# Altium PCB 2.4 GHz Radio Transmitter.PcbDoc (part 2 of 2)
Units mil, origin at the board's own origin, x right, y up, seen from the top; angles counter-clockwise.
Board outline 5905.26 x 4050.27 mil, 4 copper layers (Top Layer, GND, Power, Bottom Layer), stack 63.355 mil thick; 215 components, 108 nets, 659 pads, 107 vias.
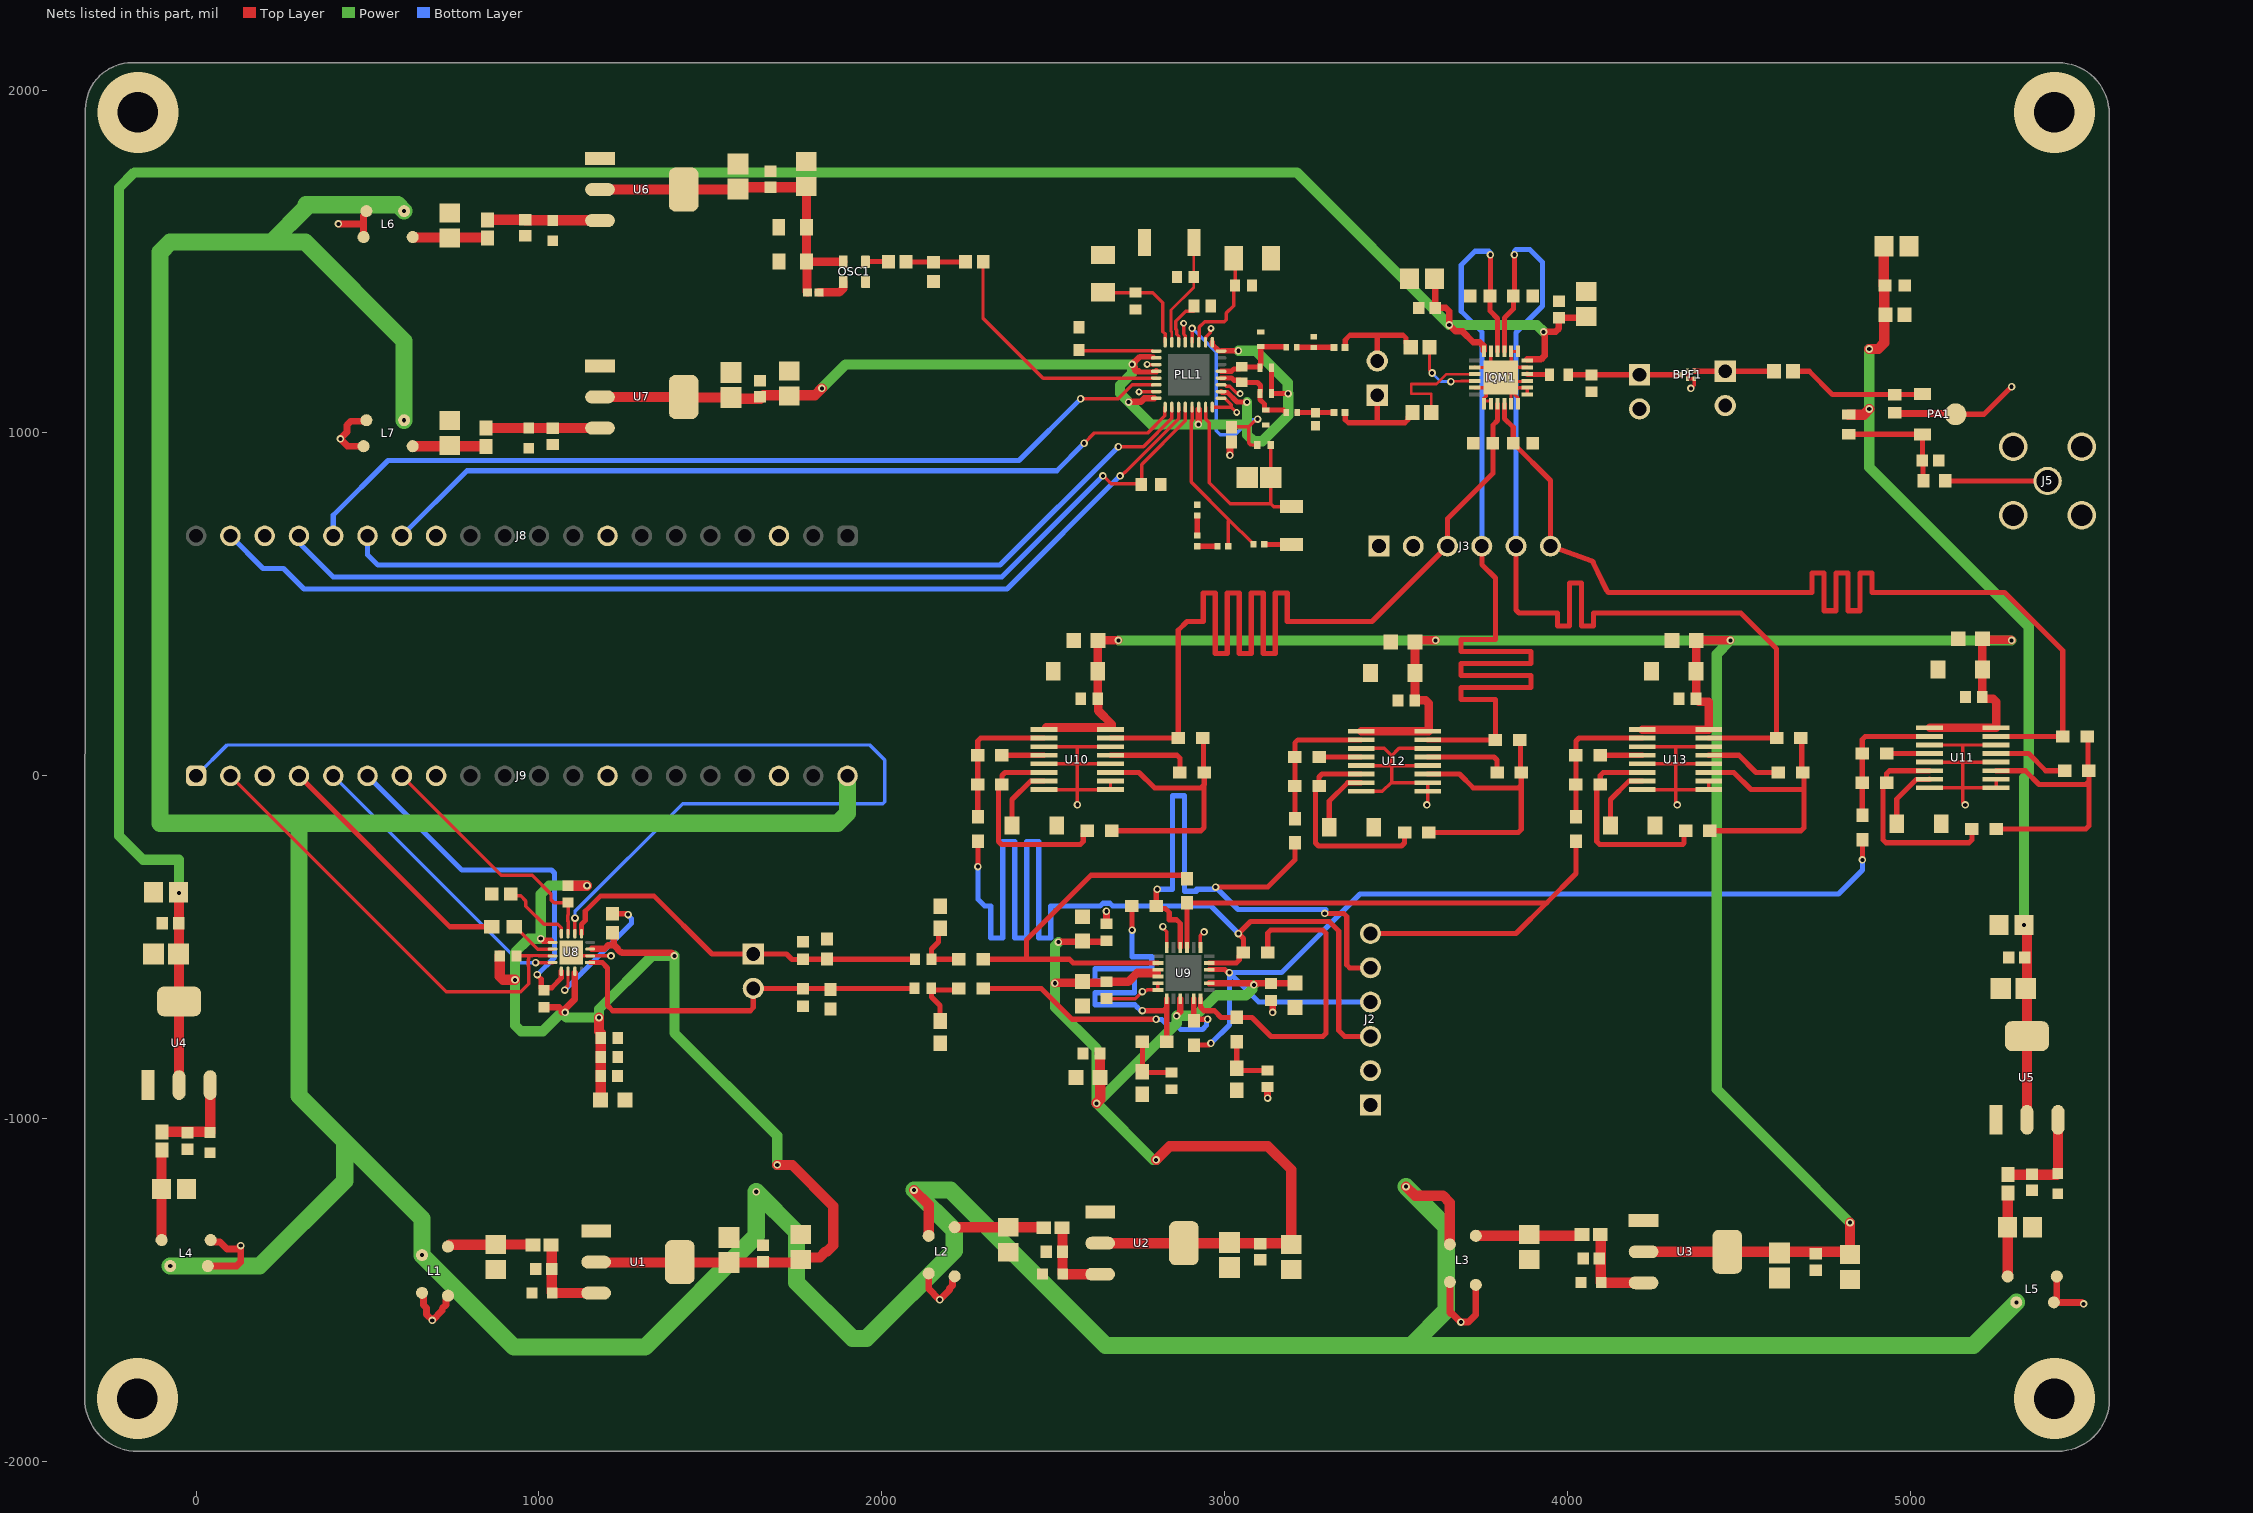
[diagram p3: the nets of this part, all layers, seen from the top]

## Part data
BPF1: library part CMP-034-000001-3, "Signal Conditioning LTCC BAND PASS FLTR 2400-2500MHz"
C1 C6 C7 C12 C13 C14 C23 C24 C25 C30 C31 C36 C37 C42 C92 C95: library part CMP-2006-01631-1, "Ceramic Capacitor, Multilayer, Ceramic, 16V, 20% +Tol, 20% -Tol, X7R, 15% TC, 0.1uF, Surface Mount, 0603"
C2 C5 C8 C11 C15 C18 C19 C22 C26 C29 C32 C35 C38 C41 C93 C94 C102: library part CMP-00075-1, "0805 10 uF 6.3 V ±10% Tolerance X7R Multilayer Ceramic Chip Capacitor"
C3 C9 C16 C20 C27 C33 C39: library part CMP-00030-45106517-1, "VJ0603Y105KXJCW1BC Multilayer Ceramic Capacitor, 1 uF, 16 V, ± 10%, X7R, 0603 [1608 Metric]"
C4 C10 C17 C21 C28 C34 C40: library part CMP-06035-051513-1, "Multilayer Ceramic Capacitors MLCC - SMD/SMT 0805 4.7uF 10%, 16VDC,  X7R 15%"
C43 C44 C46 C51 C52 C59 C60 C64 C66 C70 C72: library part CMP-00023-1, "Ceramic Capacitor, Multilayer, Ceramic, 25V, 10% +Tol, 10% -Tol, X7R, 15% TC, 0.1uF, Surface Mount, 0603"
C45 C49 C50 C57 C58 C63 C65 C69 C71: library part CMP-1035-02796-1, "CAP 10uF 6.3V ±10% 0603 (1608 Metric) Thickness 1mm SMD"
C47 C48: library part CMP-2006-04266-1, "200pF"
C53 C54 C55 C56 C61 C62 C67 C68: library part CMP-00052-1, "CGA Series 1206 100 nF 50 V ±5 % Tolerance C0G SMT Multilayer Ceramic Capacitor"
C73 C76: library part CMP-03020-021251-2, "CAP CER 1000PF 16V X7R 0402"
C74 C81: library part CMP-08246-000350-1, "Cap Ceramic 2.2pF 50V C0G 0.25pF Pad SMD 0402 +125°C Automotive T/R"
C75: library part CMP-06035-012333-1, "Ceramic Capacitor for Automotive 1.5pF ±5% 50VDC C0G 0402 Paper T/R"
C77 C78: library part CMP-2006-01663-1
C79 C80: library part CMP-08246-001196-1, "Cap Ceramic 1nF 250V C0G 5% Pad SMD 0603 +125°C Automotive T/R"
C82: library part CMP-08246-001768-1, "Cap Ceramic 1.5pF 50V C0G 0.25pF Pad SMD 0402 +125°C Automotive T/R"
C83 C85: library part CMP-06035-003994-1, "Chip Multilayer Ceramic Capacitors for General Purpose, 1206, 0.10uF, C0G, 30ppm/°C, 5%, 50V"
C84 C86 C90: library part CMP-2006-01151-1
C87: library part CMP-08246-005643-1, "Multilayer Ceramic Capacitors 2.7nF ±5% 250V C0G SMD 0805"
C88: library part CMP-03020-008489-1, "C1206 39,000 pF C0G 5.00% 50 V"
C89: library part CMP-08246-006367-1, "Multilayer Ceramic Capacitors 1.2nF ±5% 100V C0G SMD 0603"
C91: library part CMP-08246-001706-1, "Cap Ceramic 100nF 100V C0G 5% Pad SMD 1206 +125°C Automotive T/R"
C96 C98 C101 C103: library part CMP-2006-01799-1
C97: library part CMP-1035-00425-1, "CAP 6.8pF 16V ±0.5pF 0603 (1608 Metric) Thickness 1mm SMD"
C99: library part CMP-06035-025553-1, "Ceramic Capacitor 0.2pF ±0.1pF 250VDC C0G 0603 Paper T/R"
C100: library part CMP-2006-02556-2, "Chip Multilayer Ceramic Capacitors for General Purpose, 0603, 10000pF, C0G, 30ppm/°C, 5%, 50V"
C104: library part CMP-1035-00152-1, "CAP 2.2pF 16V ±0.5pF 0603 (1608 Metric) Thickness 1mm SMD"
C105: library part CMP-2006-01498-1
C106: library part CMP-2006-00028-1
FB1 FB2 FB3 FB4 FB5 FB6 FB7: library part CMP-06046-002207-1, "Chip Ferrite Bead, 0603, 180O @ 100MHz, 0.09O, 25%, 1.5A"
IQM1: library part CMP-004-000002-1, "TRF3705IRGET, Modulator Quadrature 3.1dB 3.15  3.6 V 24-Pin VQFN"
J1 J6 J7: library part CMP-02766-000084-1, "CONN HEADER VERT 2POS 2.54MM"
J2 J3: library part CMP-1681-00007-2, "Male Header, Pitch 2.54 mm, 1 x 6 Position, Height 8.38 mm, Tail Length 2.54 mm, -55 to 125 degC, RoHS, Bulk"
J4: library part CMP-02766-001428-1, "CONN HEADER VERT 2POS 2.54MM"
J5: library part CMP-009-000000-1, "Description"
J8 J9: library part CMP-1502-01348-4, "THT Vertical Socket Header WR-PHD, Pitch 2.54 mm, Single Row, 20 pins"
L1 L2 L3 L4 L5 L6 L7: library part CMP-00050-1, "Common Mode Chokes Dual 500Ohm 100MHz 1A 0.23Ohm DCR SMD T/R"
L8 L11: library part CMP-06042-009995-1, "Multilayer type RF Inductor 3.6nH ±0.2nH 0.14O 750mA 0402"
L9 L10: library part CMP-06042-014192-1, "Multilayer type Inductor for Automotive 7.5nH ±3% 0.16O 600mA 0402"
L12: library part CMP-06042-003325-1, "Wire Wound Ferrite type RF Inductor 15nH ±5% 2200mA 0.025O 0603 (1608)"
OSC1: library part CMP-00370-145325626-1, "IC 100 MHz LVCMOS Oscillator 1.8V Enable/Disable 4-VDFN"
PA1: library part CMP-09142-000059-1, "IC RF AMP 400MHZ-2.7GHZ SOT89-3"
PLL1: library part CMP-0287-00013-1, "Wideband Synthesizer with Integrated VCO, CP-32-2, Pb-Free, 1500 Reel"
R1: library part CMP-00035-1, "Res Thick Film 0603 22 Ohm 1% 0.1W(1/10W) ±200ppm/C Pad SMD Automotive T/R"
R2 R3: library part CMP-07231-005094-1, "Thick Film Chip Resistors 0603 2kO 0.1W 5% 200ppm/°C"
R4 R7 R8: library part CMP-03211-009884-1, "CRGCQ 0603 10K 5%"
R5 R6: library part CMP-26527-006412-1, "0O ±0 0.1W 0603 Thick Film Chip Resistor AEC-Q200 compliant"
R9 R10 R11 R12 R13 R14 R15 R16 R17 R18 R19 R20 R21 R22 R23 R24 R25 R26 R27 R28 R29 R30 R31 R32: library part CMP-00034-1, "Res Thin Film 0603 120K Ohm 0.1% 1/16W ±25ppm/°C Molded SMD SMD Paper T/R"
R33: library part CMP-2000-03826-1
R34: library part CMP-03211-011410-1, "RES SMD 10K OHM 1% 1/16W 0402"
R35: library part CMP-2000-03447-2, "RES Thick Film, 51O, 5%, 0.1W, 200ppm/°C, 0603"
R36: library part CMP-2000-03412-1
R37: library part CMP-2002-02756-2, "RES SMD 680 OHM 0.1% 1/16W 0402"
R38: library part CMP-02407-001090-1, "RES SMD 100 OHM 1% 1/8W 0603"
R39: library part CMP-03412-002710-1, "RES SMD 0603 1/4W 1% 100 OHM"
R40 R41 R42 R43: library part CMP-2002-08546-2, "RES Thick Film, 360O, 1%, 0.063W, 100ppm/°C, 0402"
R44 R45 R46 R47: library part CMP-00046-1, "Res Thin Film 0603 49.9 Ohm 0.1% 1/8W ±25ppm/°C Molded SMD SMD Paper T/R"
RF1 RF2 RF3 RF4 RG1 RG2 RG3 RG4: library part CMP-00029-1, "Fixed Resistor, Thin Film, 0.063W, 1000ohm, 50V, 1% +/-Tol, 50ppm/Cel, Surface Mount, 0603"
RS1 RS2 RS3 RS4: library part CMP-00028-1, "Res Thick Film 0603 50 Ohm 1% 0.1W(1/10W) ±100ppm/C Pad SMD Automotive T/R"
RT1 RT2 RT3 RT4: library part CMP-00030-1, "Resistor, thick film, SMD 0603 (1608), 52.3 ?, 0.1 W, ±1 %, CR0603-FX-52R3ELF"
U1 U2 U3 U4 U5 U6 U7: library part CMP-00032-1, "LDL1117 Series 1.2 A 3.3 V High PSRR LDO Linear Voltage Regulator-SOT-223"
U8: library part CMP-09082-000052-1, "IC DAC 16BIT V-OUT 16LFCSP"
U9: library part CMP-00021-4, "ROHS3Compliant EAR99 ADA4940 Tape & Reel (TR) op amp amplifier circuit 3mm 1.1muA 60muV 90dB"
U10 U11 U12 U13: library part CMP-00022-3, "Active Filter Dual Low Pass 8th Order 256kHz 16-Pin SSOP N"

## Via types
v1: diameter 22, hole 12, Top Layer to Bottom Layer, 88 vias
v2: diameter 19.68, hole 7.87, Top Layer to Bottom Layer, 9 vias
v3: diameter 20, hole 10, Top Layer to Bottom Layer, 6 vias
v4: diameter 236.22, hole 118.11, Top Layer to Bottom Layer, 4 vias

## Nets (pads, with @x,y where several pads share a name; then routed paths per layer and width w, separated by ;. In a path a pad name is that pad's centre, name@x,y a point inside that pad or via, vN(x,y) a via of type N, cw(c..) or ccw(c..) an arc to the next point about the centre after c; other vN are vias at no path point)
ANT: C104.2 J5.1 | length 298.5
  Top Layer w15: C104.2@5101.5,860 J5.1@5400,860
ANT1: C104.1 C106.2 L12.1 PA1.3 | length 352.2
  Top Layer w15: L12.1@4820,996.22 PA1.3@5034.88,996.22 ; PA1.3@5035.59,995.51 5034.88,994.8 C106.2@5034.88,920 5036.69,918.19 5036.69,861.81 C104.1@5038.5,860
BBI_N: IQM1.22 J3.4 R21.1 R45.1 U12.15 | length 3037.7
  Top Layer w15: U12.15@3592,105 R21.1@3789.57,105 3789.57,215.44 3789.57,222.94 3689.57,222.94 3689.57,257.94 3893.03,257.94 3893.03,292.94 3689.57,292.94 3689.57,327.94 3893.03,327.94 3893.03,362.94 3689.57,362.94 3689.57,397.94 3789.57,397.94 3789.57,415 3789.57,577.17 3750,616.73 J3.4@3750,670 ; v1(3775,1520) 3775,1401.46 R45.1@3773.54,1400 3773.54,1356.46 3795.94,1334.06 IQM1.22@3795.94,1238.54
  Bottom Layer w15: J3.4@3750,670 3750,1295 3690,1355 3690,1490 3730,1530 3770,1530 3775,1525 v1(3775,1520)
BBI_P: IQM1.21 J3.5 R22.1 R44.1 U13.15 | length 3038.7
  Top Layer w15: IQM1.21@3815.63,1238.54 3815.63,1335.63 3842.09,1362.09 3842.09,1399.37 3845,1402.28 v1(3845,1520) ; J3.5@3850,670 3850,483.79 3858.79,475 3955.4,475 3970.76,475 3970.76,437.34 4005.76,437.34 4005.76,562.15 4040.76,562.15 4040.76,437.34 4075.76,437.34 4075.76,475 4083.26,475 4505,475 4609.57,370.43 R22.1@4609.57,110 U13.15@4412,110
  Bottom Layer w15: v1(3845,1520) 3845,1530 3850,1535 3890,1535 3927.09,1497.91 3927.09,1370.47 3850,1293.39 J3.5@3850,670
BBQ_N: IQM1.9 J3.3 R9.1 R46.1 U10.15 | length 3100.4
  Top Layer w15: U10.15@2667,110 R9.1@2864.57,110 2864.57,424.57 2890,450 2930,450 2937.5,450 2937.5,533.48 2972.5,533.48 2972.5,357.02 3007.5,357.02 3007.5,533.48 3042.5,533.48 3042.5,357.02 3077.5,357.02 3077.5,533.48 3112.5,533.48 3112.5,357.02 3147.5,357.02 3147.5,533.48 3182.5,533.48 3182.5,450 3200.26,450 3430,450 J3.3@3650,670 3650,750 3782.09,882.09 R46.1@3782.09,970 3782.09,1022.51 3795.94,1036.37 IQM1.9@3795.94,1085
BBQ_P: IQM1.10 J3.6 R10.1 R47.2 U11.15 | length 3099.9
  Top Layer w15: IQM1.10@3815.63,1085 3815.63,1042.35 3841.46,1016.52 R47.2@3841.46,970 3950,861.46 J3.6@3950,670 4071.1,626.4 4075.32,622.18 4113.41,541.24 4119.65,535 4705,535 4712.5,535 4712.5,592.06 4747.5,592.06 4747.5,481.56 4782.5,481.56 4782.5,592.06 4817.5,592.06 4817.5,481.56 4852.5,481.56 4852.5,592.06 4887.5,592.06 4887.5,535 4919.18,535 5275,535 5286.13,523.87 5444.57,365.43 R10.1@5444.57,115 U11.15@5250,115
DAC_3V3: C4.1 C5.1 C6.2 C43.2 C44.2 C45.2 C46.2 R4.1 R6.1 R7.2 R8.1 U1.2 U1.4 U8.3 U8.9 U8.15 | length 3874.9
  Top Layer w15: C45.2@1179.57,-945 C45.2@1179.78,-944.78 ; C43.2@1179.78,-875.22 C43.2@1180,-875
  Top Layer w19: v1(1005,-475) 1005.81,-475 1011.75,-480.94 1034.89,-480.94 ; R7.2@1015,-674.68 1058.79,-674.68 v1@1070.05,-685.95 ; v1@1066,-690 v1@1070.05,-685.95 ; v1(1076,-690) 1074.11,-690 v1@1070.05,-685.95 ; U8.15@1104.84,-574.39 1104.84,-651.16 v1@1070.05,-685.95 ; U8.3@1154.64,-504.68 1191.5,-504.68 1202.73,-493.46 1218.47,-493.46 ; R6.1@1215,-457.6 1218.47,-461.07 1218.47,-493.46 ; 1239.25,-513.86 1240,-514.61 1238.03,-514.61 1231.78,-508.36 1231.78,-506.77 1218.47,-493.46 ; 1241.97,-514.61 1242.8,-515.43 1385.43,-515.43 v1(1395,-525)
  Top Layer w30: R4.1@885.32,-525 885.32,-585.32 895,-595 v1(930,-595) ; R8.1@1085,-320.31 1085.08,-320.24 1139.76,-320.24 v1(1140,-320) ; U1.2@1168.21,-1419.56 U1.4@1409.44,-1419.56 ; v1(1175,-705) 1175,-745.43 1179.78,-750.22 1179.78,-765 1179.78,-874.78 C43.2@1180,-875 ; C45.2@1179.78,-944.78 C43.2@1179.78,-875.22 ; U1.4@1412.3,-1419.56 1650.03,-1419.56 1651.1,-1418.48 1652.09,-1418.48 C6.2@1653.82,-1416.75 1655.55,-1418.48 1668.79,-1418.48 1669.87,-1419.56 1755.32,-1419.56 C5.1@1763.82,-1411.06 ; v1(1695,-1135) 1738.62,-1135 1858.56,-1254.94 1858.56,-1369.66 1840.99,-1387.23 1836.15,-1387.23 1818.57,-1404.81 1772.93,-1404.81 C5.1@1765.25,-1412.49
  Power w30: v1(1140,-320) 1030,-320 1005,-345 v1(1005,-475) 970,-475 930,-515 v1(930,-595) 930,-727.43 947.57,-745 1011,-745 1066,-690 1081,-705 v1(1175,-705) 1175,-680 1330,-525 v1(1395,-525) 1395,-750 1695,-1050 v1(1695,-1135)
FDA_3V3: C10.1 C11.1 C12.2 C63.2 C64.2 C65.2 C66.2 C69.2 C70.2 C71.2 C72.2 U2.2 U2.4 U9.3 U9.8 U9.21 U9.22 | length 3505.2
  Top Layer w19: v1(2515,-485) 2516.34,-483.66 2652.25,-483.66 C66.2@2655,-480.91 ; v1(2860,-700) 2860,-698.24 2870.26,-687.98 U9.3@2870.26,-650.06 ; U9.8@2955,-604.69 3077.79,-604.69 3083.11,-610 v1(3085,-610) 3086.89,-610 3092.33,-604.57 C69.2@3205,-604.57
  Top Layer w25: v1(2505,-605) 2506.34,-603.66 2651.73,-603.66 C72.2@2655,-600.39 2719.22,-600.39 2744.61,-575 2801.36,-575
  Top Layer w30: v1(2626.44,-955.43) 2626.44,-953.53 2636.73,-943.24 C63.2@2636.73,-880 2636.32,-879.59 2636.32,-810.41 C64.2@2635.91,-810 ; U2.2@2636.77,-1363.13 U2.4@2880.87,-1363.13 C11.1@3190.29,-1363.13 ; v1(2800,-1120) 2840,-1080 3125.69,-1080 3193.82,-1148.13 C11.1@3193.82,-1366.66
  Power w30: v1(2515,-485) 2505,-495 v1(2505,-605) 2505,-675 2626.44,-796.44 v1(2626.44,-955.43) ; v1(2800,-1120) 2791.02,-1120 v1(2626.44,-955.43) ; v1(3085,-610) 3080,-615 3080,-622.43 3062.43,-640 2976.16,-640 2916.16,-700 v1(2860,-700) 2860,-721.87 v1(2626.44,-955.43)
GND: BPF1.2 BPF1.3 BPF1.5 C1.1 C2.2 C3.2 C4.2 C5.2 C6.1 C7.1 C8.2 C9.2 C10.2 C11.2 C12.1 C13.1 C14.1 C15.2 C16.2 C17.2 C18.2 C19.2 C20.2 C21.2 C22.2 C23.1 C24.1 C25.1 C26.2 C27.2 C28.2 C29.2 C30.1 C31.1 C32.2 C33.2 C34.2 C35.2 C36.1 C37.1 C38.2 C39.2 C40.2 C41.2 C42.1 C43.1 C44.1 C45.1 C46.1 C47.1 C48.1 C49.1 C50.1 C51.1 C52.1 C53.2 C54.2 C55.2 C56.2 C57.1 C58.1 C59.1 C60.1 C61.2 C62.2 C63.1 C64.1 C65.1 C66.1 C67.2 C68.2 C69.1 C70.1 C71.1 C72.1 C74.2 C75.2 C79.2 C80.2 C81.2 C82.2 C83.2 C84.1 C85.2 C86.1 C87.2 C89.2 C90.1 C91.2 C92.1 C93.2 C94.1 C95.1 C99.2 C100.2 C101.1 C102.2 C105.1 C106.1 IQM1.2 IQM1.5 IQM1.7 IQM1.8 IQM1.11 IQM1.12 IQM1.13 IQM1.14 IQM1.15 IQM1.17 IQM1.19 IQM1.20 IQM1.23 IQM1.25 J2.1 J2.2 J3.1 J3.2 J5.2 J5.3 J5.4 J5.5 J6.2 J7.2 J8.3 J8.8 J8.13 J8.18 J9.3 J9.8 J9.13 J9.18 L1.1 L1.2 L2.1 L2.2 L3.1 L3.2 L4.1 L4.2 L5.1 L5.2 L6.1 L6.2 L7.1 L7.2 OSC1.2 PA1.2 PLL1.8 PLL1.9 PLL1.11 PLL1.18 PLL1.21 PLL1.27 PLL1.31 R2.1 R3.1 R5.1 R35.2 R36.2 R38.2 R39.2 R42.2 R44.2 R45.2 R46.2 R47.1 RS3.1 RS4.1 RT1.1 RT2.1 RT3.1 RT4.1 U1.1 U2.1 U3.1 U4.1 U5.1 U6.1 U7.1 U8.2 U8.17 U9.13 U9.18 U9.23 U9.24 U10.3 U10.5 U10.8 U10.9 U10.10 U10.12 U10.14 U11.3 U11.5 U11.8 U11.9 U11.10 U11.12 U11.14 U12.3 U12.5 U12.8 U12.9 U12.10 U12.12 U12.14 U13.3 U13.5 U13.8 U13.9 U13.10 U13.12 U13.14 | length 6496.7
  Top Layer w10: U8.17@1095,-515 1104.84,-524.84 1209.84,-524.84 v1(1210,-525) ; U10.8@2473,-40 2570,-40 ; U10.5@2473,35 2570,35 ; U10.3@2473,85 2570,85 ; v1(2570.63,-84.24) 2570,-83.61 2570,-40 ; C72.1@2655,-649.61 2739.39,-649.61 2759.46,-629.54 v1(2760,-629.54) 2762.3,-627.24 2771.55,-627.24 2774.42,-624.37 U9.24@2805.2,-624.37 U9.23@2805.2,-604.69 ; U10.10@2667,-15 U10.9@2667,-40 2570,-40 ; U10.12@2667,35 2570,35 ; U10.14@2667,85 2570,85 ; v3(2750,1120) 2750.71,1120.71 PLL1.31@2789.76,1120.71 ; v3(2773.6,1200) 2774,1199.61 PLL1.27@2789.76,1199.61 ; v1(2820,-440) 2820,-443.25 2830.89,-454.14 U9.18@2830.89,-500.26 ; v3(2880,1320) 2880,1288.65 2885.08,1283.57 PLL1.21@2885.08,1275.24 ; U9.13@2929.31,-500.26 2929.31,-465.69 v1(2940,-455) ; PLL1.18@2944.29,1275.24 2944.29,1278.89 2958.09,1292.69 2958.09,1303.09 v3(2960,1305) ; PLL1.8@2963.98,1075.51 3019.49,1075.51 ; PLL1.9@3000.24,1101.02 3019.49,1081.77 3019.49,1075.51 ; PLL1.11@3000.24,1140.39 3004.61,1136.02 3014.78,1136.02 3034.85,1115.96 3044.04,1115.96 v3(3045,1115) ; v3(3035,1060) 3019.49,1075.51 ; U12.8@3398,-45 3460,-45 3486.72,-18.28 ; U12.5@3398,30 3475,30 ; U12.3@3398,80 3465,80 3486.72,58.28 ; v1(3590,-85) 3592,-83 U12.9@3592,-45 U12.10@3592,-20 3488.43,-20 3486.72,-18.28 ; U12.12@3592,30 3486.72,30 ; U12.14@3592,80 3508.43,80 3486.72,58.28 ; IQM1.5@3729.02,1132.24 IQM1.25@3767.24,1132.24 ; IQM1.2@3729.02,1191.3 3778.34,1190.33 3776.26,1192.4 IQM1.23@3776.26,1238.54 ; IQM1.8@3775.47,1093.23 3755.79,1093.23 3755.79,1100.87 3762.3,1107.38 3762.3,1127.3 IQM1.25@3767.24,1132.24 ; IQM1.25@3775.47,1140.47 IQM1.25@3767.24,1132.24 ; IQM1.25@3822.56,1145 3827.62,1150.06 3869.87,1150.06 3871.73,1151.93 IQM1.15@3882.56,1151.93 ; IQM1.11@3835.12,1085.2 IQM1.25@3835.12,1119.87 ; IQM1.25@3835.32,1132.24 IQM1.14@3882.56,1132.24 IQM1.13@3882.56,1112.56 ; IQM1.25@3838.15,1119.87 3855,1103.02 IQM1.12@3855,1085 ; IQM1.19@3855,1238.54 3854.09,1237.64 3836.22,1237.64 IQM1.20@3835.32,1238.54 3835.32,1206.97 3819.25,1190.91 3805.79,1190.91 IQM1.25@3805.79,1161.77 ; IQM1.17@3882.56,1191.3 3835.32,1191.3 IQM1.25@3805.79,1161.77 ; U13.8@4218,-40 4315,-40 ; U13.5@4218,35 4315,35 ; U13.3@4218,85 4315,85 ; v1(4320,-85) 4315,-80 4315,-40 ; BPF1.5@4350,1181.34 BPF1.2@4350,1158.7 BPF1.3@4369.69,1158.7 4369.69,1139.69 v1(4360,1130) ; U13.10@4412,-15 U13.9@4412,-40 4315,-40 ; U13.12@4412,35 4315,35 ; U13.14@4412,85 4315,85 ; U11.8@5056,-35 5153,-35 ; U11.5@5056,40 5153,40 ; U11.3@5056,90 5153,90 ; v1(5160,-85) 5153,-78 5153,-35 ; U11.10@5250,-10 U11.9@5250,-35 5153,-35 ; U11.12@5250,40 5153,40 ; U11.14@5250,90 5153,90 ; 2570,-40 2570,35 ; 2570,35 2570,85 ; 3475,30 3486.72,41.72 ; 3475,30 3486.72,30 ; 3486.72,-18.28 3486.72,30 ; 3486.72,30 3486.72,41.72 ; 3486.72,41.72 3486.72,58.28 ; IQM1.25@3767.24,1132.24 3776.26,1132.24 IQM1.25@3805.79,1161.77 ; 4315,-40 4315,35 ; 4315,35 4315,85 ; 5153,-35 5153,40 ; 5153,40 5153,90
  Top Layer w15: PA1.2@5131.73,1054.57 5214.57,1054.57 v1(5295,1135)
  Top Layer w20: L4.1@34.14,-1429.75 118.28,-1429.75 130,-1418.04 v1(130,-1370) 120,-1380 89.76,-1380 69.64,-1359.88 55.49,-1359.88 49.58,-1353.97 L4.2@42.51,-1353.97 ; v1(415,1610) 481.45,1610 488.4,1603.05 ; L7.2@488.4,961.37 441.94,961.37 v1(420.59,982.72) 420.59,983.26 440.45,1003.11 440.45,1022.57 452.16,1034.29 493.89,1034.29 L7.1@496.76,1037.16 ; L6.2@488.4,1571.37 488.4,1603.05 ; L6.1@496.76,1647.16 496.76,1643.1 488.4,1634.73 488.4,1603.05 ; L1.1@658.82,-1507.87 658.82,-1514.79 663.26,-1519.23 663.26,-1543.36 672.05,-1552.15 672.05,-1570.81 688.82,-1587.58 v1(688.82,-1588.13) 717.76,-1559.19 717.76,-1554.3 728.69,-1543.36 728.69,-1529.22 734.61,-1523.31 L1.2@734.61,-1516.24 ; L2.1@2136.66,-1451.36 2136.66,-1495.97 v1(2168.82,-1528.13) 2197.75,-1499.2 2197.75,-1495.65 2206.54,-1486.86 2206.54,-1472.72 2212.45,-1466.8 L2.2@2212.45,-1459.73 ; C66.1@2655,-431.69 v1(2655,-395) ; v1(3015,935) 3015.38,935.38 3015.38,969.1 C89.2@3020,973.72 ; v1(3125,-940) RS4.1@3125,-907.56 ; C70.1@3135,-655 3140,-660 v1(3140,-690) ; L3.1@3656.66,-1476.36 3656.66,-1565.97 3658.82,-1568.13 3663.28,-1568.13 3688.28,-1593.13 v1(3688.82,-1593.13) 3689.2,-1592.74 3711.47,-1592.74 3732.45,-1571.76 L3.2@3732.45,-1484.73 ; C105.1@4955,1058.43 4956.93,1056.5 5129.8,1056.5 PA1.2@5131.73,1054.57 ; L5.2@5426.94,-1460.14 5426.94,-1523.5 5418.57,-1531.87 L5.1@5418.57,-1535.93 5500.93,-1535.93 v1(5505,-1540)
  other v4: -171.08,-1816.32 5420,-1816.32 -170,1935 5420,1935
IN1_N: RF1.1 RG3.2 U9.1 | length 1086.2
  Top Layer w15: RF1.1@2729.57,-380 2729.78,-380.22 2729.78,-449.78 v1(2730,-450) ; v1(2760,-685) 2821.79,-685 2830.89,-675.9 ; RG3.2@2830.43,-775.77 2830.89,-775.32 2830.89,-675.9 ; U9.1@2830.89,-650.06 2830.89,-675.9
  Bottom Layer w15: v1(2730,-450) 2730,-518.84 2730,-527.55 2787.27,-527.55 2787.27,-562.55 2621.72,-562.55 2621.72,-597.55 2736.5,-597.55 2736.5,-632.55 2621.72,-632.55 2621.72,-667.55 2737.55,-667.55 2745.05,-675.05 2755,-685 v1(2760,-685)
IN1_P: RF3.2 RG2.1 U9.20 | length 1121.2
  Top Layer w15: RG2.1@2295.43,-535 2421.53,-535 ; U9.20@2805.2,-545.63 2558.26,-545.63 2547.63,-535 2421.53,-535 ; RF3.2@2890,-299.57 2880.43,-290 2610,-290 2421.53,-478.47 2421.53,-535
IN2_N: RF4.2 RG4.2 U9.6 | length 954.6
  Top Layer w15: U9.6@2929.31,-650.06 2929.31,-674.31 2940,-685 2970,-685 2989.57,-704.57 RG4.2@3035,-704.57 3035.43,-705 3080,-705 3135,-760 3286.21,-760 3295,-751.21 3295,-458.79 3286.21,-450 3134.22,-450 3125.43,-458.79 RF4.2@3125.43,-515
IN2_P: RF2.1 RG1.2 U9.5 | length 831.2
  Top Layer w15: RG1.2@2295.43,-620 2465,-620 2555,-710 v1(2800,-710) ; RF2.1@2909.63,-714.2 U9.5@2909.63,-650.06 ; RF2.1@2910,-713.72 2913.72,-710 v1(2950,-710)
  Bottom Layer w15: v1(2800,-710) 2801.05,-711.05 2816.33,-711.05 2830.89,-725.61 2857.32,-725.61 2871.72,-740 2935,-740 2947.32,-727.68 2947.32,-712.68 v1(2950,-710)
IOUT_N: J2.5 R29.1 RF1.2 U9.16 | length 1904
  Top Layer w15: v1(2803.14,-330.64) 2800.43,-333.35 RF1.2@2800.43,-380 2807.87,-387.43 2827.43,-387.43 2838.14,-398.14 2838.14,-419.55 2859.55,-419.55 2870.26,-430.26 U9.16@2870.26,-500.26 ; v1(2973.51,-324.54) 3125.46,-324.54 3205,-245 R29.1@3205,-195.87 ; v1(3291.94,-401.11) 3347.33,-401.11 3356.11,-409.9 3356.11,-551.21 3364.9,-560 J2.5@3425,-560
  Bottom Layer w8: v1(3291.94,-401.11) v1@3295,-398.05
  Bottom Layer w15: v1(2803.14,-330.64) 2840,-330.64 2847.5,-330.64 2847.5,-57.94 2882.5,-57.94 2882.5,-336.43 2917.5,-336.43 2917.5,-330.64 2969.36,-330.64 v1@2970,-330 ; v1(2973.51,-324.54) 3038.97,-390 3295,-390 v1@3295,-398.05
IOUT_P: J2.6 R31.1 RF3.1 U9.15 | length 1946
  Top Layer w15: U9.15@2889.94,-500.26 2889.94,-370.49 RF3.1@2890,-370.43 3939.57,-370.43 ; J2.6@3425,-460 3850,-460 3939.57,-370.43 ; R31.1@4025,-190.87 4025,-285 3939.57,-370.43
LO1_N: C98.2 IQM1.4 | length 213.3
  Top Layer w8: C98.2@3597.56,1250 3597.56,1182.44 v1(3605,1175) ; v1(3660,1150) 3660.97,1150.97 3688.34,1150.97 3689.31,1151.93 IQM1.4@3729.02,1151.93
  Bottom Layer w8: v1(3605,1175) 3630,1150 v1(3660,1150)
LO1_P: C96.2 IQM1.3 | length 337.8
  Top Layer w8: C96.2@3602.56,1060 3602.56,1110.68 3602.56,1114.68 3544.22,1114.68 3544.22,1142.68 3617.68,1142.68 3625.44,1150.44 3646.61,1171.61 IQM1.3@3729.02,1171.61
LO2_N: C81.1 L10.2 L11.1 PLL1.13 R33.1 | length 266.7
  Top Layer w15: PLL1.13@2997.74,1179.84 2989.8,1179.84 2989.49,1180.16 2997.77,1180.16 2997.93,1180 3020.31,1180 3026.66,1186.36 3043.72,1186.36 R33.1@3050,1192.64 3100.63,1192.64 L10.2@3103.27,1190 3103.88,1190.61 3103.88,1200.55 3105,1201.67 C81.1@3105,1251.69 3178.88,1251.69 3179.25,1251.32 L11.1@3179.25,1250
LO2_P: C74.1 L8.1 L9.2 PLL1.12 R33.2 | length 265.4
  Top Layer w15: PLL1.12@2989.49,1160.16 2989.65,1160 3020.31,1160 3026.66,1153.64 3044.17,1153.64 R33.2@3050,1147.81 ; R33.2@3050,1147.36 3095.69,1147.36 3104.48,1138.58 3104.48,1120.89 3103.27,1119.69 3103.27,1097.18 3116.54,1083.91 C74.1@3116.54,1066.82 ; C74.1@3120,1066.65 3170.84,1066.65 3175.15,1062.34 3179.63,1062.34 3180,1061.97 L8.1@3180,1060
LO3_N: C76.1 C82.1 L11.2 | length 108.5
  Top Layer w15: L11.2@3210.75,1250 C76.1@3319.25,1250
LO3_P: C73.1 C75.1 L8.2 | length 107.8
  Top Layer w15: L8.2@3211.5,1060 C73.1@3319.25,1060
LO_N: C76.2 C98.1 J4.2 | length 315.5
  Top Layer w15: C76.2@3350.75,1250 3351.52,1250.77 3351.52,1271.52 3365,1285 3445,1285 ; J4.2@3445,1210 3445,1285 ; C98.1@3542.44,1250 3529.27,1263.17 3529.27,1276.21 3520.48,1285 3445,1285
LO_P: C73.2 C96.1 J4.1 | length 318.1
  Top Layer w15: C73.2@3350.75,1060 3351.83,1058.92 3351.83,1038.79 3360.61,1030 3445,1030 ; J4.1@3445,1110 3445,1030 ; C96.1@3547.44,1060 3534.27,1046.83 3534.27,1038.79 3525.48,1030 3445,1030
LPF_3V3: C17.1 C18.1 C23.2 C49.2 C50.2 C51.2 C52.2 C53.1 C54.1 C57.2 C58.2 C59.2 C60.2 C61.1 C62.1 U3.2 U3.4 U10.1 U10.16 U11.1 U11.16 U12.1 U12.16 U13.1 U13.16 | length 7402.4
  Top Layer w25: U10.1@2480,141 2670.25,141 2670.25,151.05 2631.2,190.1 2631.2,223.4 C51.2@2629.61,225 ; C51.2@2629.96,227.32 C53.1@2629.96,305 C49.2@2629.96,385.85 ; C49.2@2630.43,395 v1(2690,395) ; U12.1@3398,130 U12.16@3592,130 3594.5,130 3595,130.5 3595,211.21 3586.21,220 C59.2@3554.61,220 3555.02,220.41 3555.02,389.59 C57.2@3555.43,390 3560.43,395 v1(3615,395) ; U13.1@4218,135 U13.16@4412,135 4412,216.21 4382.85,216.21 4374.61,224.46 C60.2@4374.61,225 4375.02,225.41 4375.02,394.59 C58.2@4375.43,395 v1(4475,395) ; U11.1@5056,140 U11.16@5250,140 5250,216.21 5241.21,225 5214.61,225 C52.2@5209.61,230 5210.02,230.41 5210.02,399.59 5213.27,396.34 5293.66,396.34 v1(5295,395)
  Top Layer w30: U3.2@4221.77,-1388.13 U3.4@4465.87,-1388.13 4815.28,-1388.13 C18.1@4823.82,-1396.66 v1(4823.82,-1303.13)
  Power w30: v1(2690,395) v1(3615,395) v1(4475,395) ; v1(4823.82,-1303.13) 4630.69,-1110 4435,-914.31 4435,355 v1(4475,395) ; v1(5295,395) v1(4475,395)
MODULATOR_3V3: C21.1 C22.1 C24.2 C92.2 C93.1 C94.2 C95.2 IQM1.18 IQM1.24 U4.2 U4.4 | length 7716.4
  Top Layer w19: C93.1@3611.47,1450 3613.62,1447.84 C92.2@3613.62,1365 3645,1365 3655,1355 v1(3655,1315) 3673.78,1296.22 3693.78,1296.22 3725,1265 3744,1265 3755,1254 IQM1.24@3755,1240 ; IQM1.18@3882.56,1214.58 3922.37,1214.58 3933.5,1225.71 3933.5,1290.68 3930,1294.19 v1(3930,1295) 3965,1295 3975,1305 C95.2@3975,1336.38 4051.38,1336.38 C94.2@4055,1340
  Top Layer w30: U4.2@-49.69,-902.05 U4.4@-49.69,-657.95 v1(-49.69,-342.07)
  Power w30: v1(-49.69,-342.07) -50,-341.75 -50,-245 -155,-245 -225,-175 -225,1715 -180,1760 3210,1760 v1(3655,1315) 3910,1315 v1(3930,1295)
NetBPF1_1: BPF1.1 C97.2 C99.1 J6.1 | length 328.1
  Top Layer w15: C97.2@4002.56,1170 4002.74,1169.82 4069.82,1169.82 C99.1@4070,1169.64 4329.95,1169.64 BPF1.1@4330.31,1170
NetC1_2: C1.2 C3.1 FB1.2 U1.3 | length 269.6
  Top Layer w30: FB1.2@1035.44,-1368.13 1037.13,-1369.82 1037.13,-1506.43 C3.1@1038.82,-1508.13 1039.1,-1508.4 1166.5,-1508.4 U1.3@1166.77,-1508.68
NetC2_1: C2.1 FB1.1 L1.3 | length 250.8
  Top Layer w30: L1.3@734.61,-1373.03 739.83,-1367.8 846.99,-1367.8 848.13,-1366.66 C2.1@873.82,-1366.66 980.74,-1366.66 FB1.1@982.2,-1368.13
NetC7_2: C7.2 C9.1 FB2.2 U2.3 | length 245.1
  Top Layer w30: FB2.2@2525.44,-1318.13 2526.66,-1319.34 2526.66,-1451.91 C9.1@2527.88,-1453.13 2528.15,-1453.4 2636.5,-1453.4 U2.3@2636.77,-1453.68
NetC8_1: C8.1 FB2.1 L2.3 | length 260.4
  Top Layer w30: L2.3@2212.45,-1316.52 2470.6,-1316.52 FB2.1@2472.2,-1318.13
NetC13_2: C13.2 C16.1 FB3.2 U3.3 | length 264.9
  Top Layer w30: FB3.2@4095.44,-1338.13 4096.89,-1339.58 4096.89,-1476.67 C16.1@4098.35,-1478.13 4098.62,-1478.4 4221.5,-1478.4 U3.3@4221.77,-1478.68
NetC14_2: C14.2 C20.1 FB4.2 U4.3 | length 279.5
  Top Layer w30: FB4.2@-99.69,-1038.38 38.23,-1038.38 C20.1@40.31,-1040.47 40.87,-1039.92 U4.3@40.87,-902.05
NetC15_1: C15.1 FB3.1 L3.3 | length 311.2
  Top Layer w30: L3.3@3732.45,-1341.52 4038.8,-1341.52 FB3.1@4042.2,-1338.13
NetC19_1: C19.1 FB4.1 L4.3 | length 262.8
  Top Layer w30: L4.3@-100.7,-1353.97 -100.7,-1092.63 FB4.1@-99.69,-1091.62
NetC25_2: C25.2 C27.1 FB5.2 U5.3 | length 303.4
  Top Layer w30: FB5.2@5285,-1163.38 5426.62,-1163.38 C27.1@5430,-1160 5430.55,-1159.45 U5.3@5430.55,-1003.22
NetC26_1: C26.1 FB5.1 L5.3 | length 244
  Top Layer w30: L5.3@5283.73,-1460.14 5283.73,-1217.89 FB5.1@5285,-1216.62
NetC31_2: C31.2 C33.1 FB6.2 U6.3 | length 329.4
  Top Layer w30: FB6.2@850,1621.62 959.37,1621.62 C31.2@960,1622.24 961.4,1620.85 1176.55,1620.85 U6.3@1177.95,1619.45
NetC32_1: C32.1 FB6.1 L6.3 | length 219.6
  Top Layer w30: L6.3@631.6,1571.37 633.1,1569.88 848.51,1569.88 FB6.1@850,1568.38
NetC37_2: C37.2 C39.1 FB7.2 U7.3 | length 332.6
  Top Layer w30: FB7.2@845.59,1014.34 845.78,1014.53 C39.1@970,1014.53 ; C39.1@970,1014.72 1040,1014.72 1177.68,1014.72 U7.3@1177.95,1014.45
NetC38_1: C38.1 FB7.1 L7.3 | length 214.1
  Top Layer w30: L7.3@631.6,961.37 845.32,961.37 FB7.1@845.59,961.1
NetC55_1: C55.1 U10.7 | length 191.2
  Top Layer w15: C55.1@2380.04,-145 2380.04,-69.28 2433.82,-15.5 2472.5,-15.5 U10.7@2473,-15
NetC56_1: C56.1 U11.7 | length 192.4
  Top Layer w15: C56.1@4960.04,-140 4960.04,-67.28 5016.82,-10.5 5055.5,-10.5 U11.7@5056,-10
NetC67_1: C67.1 U12.7 | length 191.5
  Top Layer w15: C67.1@3305.04,-150 3305.04,-73.75 3358.79,-20 U12.7@3398,-20
NetC68_1: C68.1 U13.7 | length 191.2
  Top Layer w15: C68.1@4125.04,-145 4125.04,-69.28 4178.82,-15.5 4217.5,-15.5 U13.7@4218,-15
NetC77_1: C77.1 OSC1.3 | length 67.1
  Top Layer w15: OSC1.3@1952.48,1499.53 1952.72,1499.76 2019.17,1499.76 C77.1@2019.41,1500
NetC77_2: C77.2 C78.1 R35.1 | length 175.3
  Top Layer w15: C77.2@2070.59,1500 2071.51,1499.08 2149.08,1499.08 R35.1@2150,1498.17 2150.92,1499.08 2243.49,1499.08 C78.1@2244.41,1500
NetC78_2: C78.2 PLL1.29 | length 743.3
  Top Layer w10: C78.2@2295.59,1500 2295,1499.41 2295,1335 2470,1160 2800.35,1160 PLL1.29@2800.51,1160.16
NetC83_1: C83.1 C84.2 PLL1.19 | length 313.7
  Top Layer w10: PLL1.19@2924.61,1275.24 2926,1276.63 2926,1309.14 2941.86,1325 2999.14,1325 3005,1330.86 3005,1350 3026.67,1371.67 3026.67,1430 3030.39,1433.72 3030.39,1506.28 C83.1@3026.67,1510
NetC85_1: C85.1 C86.2 PLL1.24 | length 305.8
  Top Layer w10: C85.1@2646.23,1409.61 C86.2@2740,1409.61 2790.39,1409.61 2819.61,1380.39 2819.61,1295.39 2826.1,1288.9 PLL1.24@2826.1,1264.49
  Top Layer w15: C85.1@2645,1410.84 C85.1@2646.23,1409.61
NetC87_1: C87.1 C88.1 PLL1.7 R37.1 | length 665
  Top Layer w10: PLL1.7@2944.21,1075.51 2944.21,1040.79 2955,1030 2955,855 3016.1,793.9 3134.02,793.9 ; C87.1@3134.02,870 3134.02,793.9 ; C87.1@3134.68,870 R37.1@3134.68,965 ; C88.1@3195,785.12 3142.8,785.12 3134.02,793.9
NetC88_2: C88.2 R40.1 | length 79.3
  Top Layer w15: R40.1@3115.83,675 C88.2@3195.12,675
NetC89_1: C89.1 PLL1.20 R37.2 | length 673.3
  Top Layer w10: PLL1.20@2904.84,1264.49 2904.92,1264.57 v1(2904.92,1304.92) ; C89.1@3020,1016.28 3021.65,1017.93 3070,1017.93 ; R37.2@3095.31,965 3075.86,965 3070,970.86 3070,1017.93 ; v1(3096,1040.37) 3092.75,1040.37 3077.38,1025 3077.07,1025 3070,1017.93
  Bottom Layer w10: v1(2904.92,1304.92) 2905.08,1304.92 2975,1235 2975,1006.54 2986.54,995 3030,995 3073.07,1038.07 3093.7,1038.07 v1(3096,1040.37)
NetC90_2: C90.2 C91.1 PLL1.23 | length 319.3
  Top Layer w8: PLL1.23@2845.79,1264.49 2845.79,1294.66 2843.5,1296.95 2843.5,1358.5 2910,1425 2910,1454.61 C90.2@2909.61,1455 2909.61,1554.61 C91.1@2910,1555
NetJ8_14: J8.14 PLL1.1 | length 2395.9
  Top Layer w10: v1(2590,970) 2620,1000 2775,1000 2825,1050 2825,1074.41 PLL1.1@2826.1,1075.51
  Bottom Layer w15: J8.14@600,700 790,890 2510,890 v1(2590,970)
NetJ8_15: J8.15 PLL1.2 | length 2623.3
  Top Layer w10: v1(2690,960) 2763.28,960 2845.79,1042.5 PLL1.2@2845.79,1075.51
  Bottom Layer w15: J8.15@500,700 500,645 530,615 2345,615 v1(2690,960)
NetJ8_16: J8.16 PLL1.30 | length 2607.5
  Top Layer w10: v1(2580,1100) 2690,1100 2730.6,1140.6 2769.63,1140.6 2769.76,1140.47 PLL1.30@2789.76,1140.47
  Bottom Layer w15: J8.16@400,700 400,760 560,920 2400,920 v1(2580,1100)
NetJ8_17: J8.17 PLL1.4 R38.1 | length 2932
  Top Layer w10: v1(2645,875) 2645.38,875 2668.88,851.5 R38.1@2757.78,851.5 ; R38.1@2756.28,850 R38.1@2757.78,851.5 ; R38.1@2757.78,853.44 R38.1@2757.78,851.5 ; PLL1.4@2885.16,1075.51 2885.16,1035.16 2758.08,908.08 2758.08,851.8 R38.1@2757.78,851.5
  Bottom Layer w15: J8.17@300,700 300,680 400,580 2350,580 v1(2645,875)
NetJ8_19: J8.19 PLL1.3 | length 3069.8
  Top Layer w10: v1(2695,875) 2698.25,875 2708.25,885 2709.5,885 2865.79,1041.29 PLL1.3@2865.79,1075.51
  Bottom Layer w15: J8.19@100,700 195,605 255,605 315,545 2365,545 v1(2695,875)
NetJ9_1: J9.1 U8.6 | length 3287.7
  Top Layer w10: U8.6@1104.37,-460.51 1104.68,-460.2 1104.68,-415.32 v1(1105,-415)
  Bottom Layer w10: J9.1@0,0 90,90 1965,90 2008.79,46.21 2008.79,-75.36 2002.93,-81.21 1418.79,-81.21 1105,-395 v1(1105,-415)
NetJ9_2: J9.2 R4.2 U8.11 | length 1328.8
  Top Layer w10: J9.2@100,0 730,-630 946.21,-630 970,-606.21 970,-554.7 969,-553.7 969,-536.3 970,-535.3 970,-525.05 ; R4.2@934.68,-525 R4.2@934.68,-525 970,-525.05 ; U8.11@1039.78,-525.1 1039.73,-525.05 999.75,-525.05 998.7,-524 981.3,-524 980.25,-525.05 970,-525.05
NetJ9_4: J9.4 R1.1 | length 744.7
  Top Layer w15: J9.4@300,0 740,-440 R1.1@862.44,-440
NetJ9_5: J9.5 U8.12 | length 865.6
  Top Layer w10: v1(990,-545) 990.11,-544.89 1039.67,-544.89 U8.12@1039.78,-544.78
  Bottom Layer w10: J9.5@400,0 945,-545 v1(990,-545)
NetJ9_6: J9.6 R7.1 U8.13 | length 1118.3
  Top Layer w15: v1(995,-580) 995,-581.89 1006.51,-593.41 1006.51,-617.89 1013.94,-625.32 R7.1@1015,-625.32 1022.42,-617.89 1037.11,-617.89 1065,-590 U8.13@1065,-570
  Bottom Layer w15: J9.6@500,0 775,-275 1036.21,-275 1045,-283.79 1045,-530 v1(995,-580)
NetJ9_7: J9.7 R8.2 U8.7 | length 739.3
  Top Layer w10: J9.7@600,0 890,-290 980,-290 1035,-345 1035,-361.21 1043.79,-370 1084.69,-370 R8.2@1084.84,-369.84 ; U8.7@1084.69,-460.51 1084.84,-460.35 1084.84,-424.54 1084,-423.7 1084,-406.3 1084.84,-405.46 R8.2@1084.84,-369.84 ; R8.2@1085,-369.68 R8.2@1084.84,-369.84
NetOSC1_1: OSC1.1 R34.2 | length 94.6
  Top Layer w25: R34.2@1816.78,1410 1876.21,1410 1887.52,1421.31 OSC1.1@1887.52,1440.47
NetPLL1_5: PLL1.5 R40.2 R41.1 | length 553.7
  Top Layer w10: PLL1.5@2904.84,1075.51 2904.84,1036.33 2902.21,1033.7 2902.21,856.96 3013.66,745.51 ; R41.1@3010.83,670 3010.83,742.68 3013.66,745.51 ; R40.2@3084.17,675 3084.17,675.08 3079.95,679.3 3079.87,679.3 3013.66,745.51
NetPLL1_22: PLL1.22 R36.1 | length 118.4
  Top Layer w10: PLL1.22@2865.39,1275.24 2865.39,1282.04 2859.79,1287.65 2859.79,1300.46 2857.5,1302.75 2857.5,1325.78 2886.72,1355 R36.1@2910,1355
NetPLL1_25: PLL1.25 R39.1 | length 217.6
  Top Layer w8: R39.1@2568.46,1240 R39.1@2569.57,1238.9
  Top Layer w10: R39.1@2574.57,1238.9 2575.67,1240 2788.74,1240 PLL1.25@2789.76,1238.98
NetR1_2: R1.2 U8.10 | length 139.3
  Top Layer w10: R1.2@927.56,-440 930.43,-440 995.84,-505.41 U8.10@1039.78,-505.41
NetR5_2: R5.2 U8.8 | length 214.2
  Top Layer w10: R5.2@917.6,-345 922.25,-349.65 946.55,-349.65 961.94,-365.04 961.94,-380.04 1014.71,-432.81 1054.71,-432.81 1065,-443.1 U8.8@1065,-460.51
NetR6_2: R6.2 U8.14 | length 410
  Top Layer w10: v1(1075,-625) 1075,-621.75 1084.69,-612.07 U8.14@1084.69,-570
  Top Layer w15: R6.2@1215,-402.4 1257.4,-402.4 v1(1260,-405)
  Bottom Layer w15: v1(1075,-625) 1270,-430 1270,-416.89 1260,-406.89 v1(1260,-405)
NetR9_2: R9.2 R12.2 R18.2 U10.11 | length 833.1
  Top Layer w15: U10.11@2667,10 2750,10 2795,-35 2930,-35 2940.43,-24.57 ; R18.2@2670.43,-160 2931.21,-160 2940,-151.21 2940,-25 2940.43,-24.57 ; R9.2@2935.43,110 2937.93,107.5 2937.93,12.5 R12.2@2940.43,10 2940.43,-24.57
NetR10_2: R10.2 R14.2 R20.2 U11.11 | length 827.6
  Top Layer w15: U11.11@5250,15 5335,15 5375,-25 5511.65,-25 5520.43,-16.21 ; R20.2@5250.43,-155 5511.65,-155 5520.43,-146.21 5520.43,-16.21 ; R10.2@5515.43,115 5517.93,112.5 5517.93,17.5 R14.2@5520.43,15 5520.43,-16.21
NetR11_1: R11.1 R15.1 R17.2 U10.2 | length 418.5
  Top Layer w15: R17.2@2280,-120 2279.78,-119.78 2279.78,-25 2279.78,59.78 R11.1@2279.56,60 2279.56,101.21 2288.35,110 U10.2@2473,110
NetR11_2: R11.2 U10.4 | length 122.6
  Top Layer w15: R11.2@2350.43,60 U10.4@2473,60
NetR12_1: R12.1 U10.13 | length 247.4
  Top Layer w15: U10.13@2667,60 2860.78,60 2869.57,51.21 R12.1@2869.57,10
NetR13_1: R13.1 R16.1 R19.2 U11.2 | length 421.5
  Top Layer w15: R19.2@4860,-115 4859.78,-114.78 4859.78,64.78 R13.1@4859.57,65 4859.57,106.21 4868.35,115 U11.2@5056,115
NetR13_2: R13.2 U11.4 | length 125.6
  Top Layer w15: R13.2@4930.43,65 U11.4@5056,65
NetR14_1: R14.1 U11.13 | length 220.3
  Top Layer w15: U11.13@5250,65 5345,65 5395,15 R14.1@5449.57,15
NetR15_2: R15.2 R18.1 U10.6 | length 615.2
  Top Layer w15: U10.6@2473,10 2359.22,10 2350.43,1.21 R15.2@2350.43,-25 2350.22,-25 2340,-35.22 2340,-191.21 2348.79,-200 2578.59,-200 2587.38,-191.21 2587.38,-170.21 2597.6,-160 R18.1@2599.57,-160
NetR16_2: R16.2 R20.1 U11.6 | length 624.1
  Top Layer w15: U11.6@5056,15 4939.22,15 4930.43,6.21 R16.2@4930.43,-20 4930.22,-20 4920,-30.22 4920,-186.21 4928.79,-195 5170.78,-195 5179.57,-186.21 R20.1@5179.57,-155
NetR21_2: R21.2 R24.2 R30.2 U12.11 | length 830.3
  Top Layer w15: U12.11@3592,5 3685,5 3725,-35 3856.65,-35 3865.43,-26.21 ; R30.2@3595.43,-165 3856.21,-165 3865,-156.21 3865,9.57 R24.2@3865.43,10 3862.93,12.5 3862.93,102.5 R21.2@3860.43,105
NetR22_2: R22.2 R26.2 R32.2 U13.11 | length 842.1
  Top Layer w15: U13.11@4412,10 4485,10 4535,-40 4690,-40 ; R32.2@4415.43,-160 4681.21,-160 4690,-151.21 4690,-40 ; R22.2@4680.43,110 4682.93,107.5 4682.93,12.5 R26.2@4685.43,10 4690,5.43 4690,-40
NetR23_1: R23.1 R27.1 R29.2 U12.2 | length 418.5
  Top Layer w15: R29.2@3205,-125 3204.78,-124.78 3204.78,54.78 R23.1@3204.56,55 3204.56,96.21 3213.35,105 U12.2@3398,105
NetR23_2: R23.2 U12.4 | length 122.6
  Top Layer w15: R23.2@3275.43,55 U12.4@3398,55
NetR24_1: R24.1 U12.13 | length 242.4
  Top Layer w15: U12.13@3592,55 3785.78,55 3794.57,46.21 R24.1@3794.57,10
NetR25_1: R25.1 R28.1 R31.2 U13.2 | length 418.5
  Top Layer w15: R31.2@4025,-120 4024.78,-119.78 4024.78,59.78 R25.1@4024.56,60 4024.56,101.21 4033.35,110 U13.2@4218,110
NetR25_2: R25.2 U13.4 | length 122.6
  Top Layer w15: R25.2@4095.43,60 U13.4@4218,60
NetR26_1: R26.1 U13.13 | length 223.3
  Top Layer w15: U13.13@4412,60 4500,60 4550,10 R26.1@4614.57,10
NetR27_2: R27.2 R30.1 U12.6 | length 621.1
  Top Layer w15: U12.6@3398,5 3284.22,5 3275.43,-3.79 R27.2@3275.43,-30 3275.22,-30 3265,-40.22 3265,-196.21 3273.79,-205 3515.78,-205 3524.57,-196.21 R30.1@3524.57,-165
NetR28_2: R28.2 R32.1 U13.6 | length 621.4
  Top Layer w15: U13.6@4218,10 4104.22,10 4095.43,1.21 R28.2@4095.43,-25 4095.22,-25 4085,-35.22 4085,-191.21 4093.79,-200 4336.21,-200 4340,-196.21 4340,-164.57 R32.1@4344.57,-160
NetR41_2: R41.2 R43.1 | length 59.5
  Top Layer w15: R43.1@2920,669.17 2920.42,669.58 2978.75,669.58 R41.2@2979.17,670
NetR42_1: R42.1 R43.2 | length 58.3
  Top Layer w15: R43.2@2920,700.83 R42.1@2920,759.17
NetRG1_1: RG1.1 RS1.2 RT1.2 | length 199.1
  Top Layer w15: RT1.2@2170,-715 2170,-670 2145,-645 RS1.2@2145,-625 ; RG1.1@2224.57,-620 2219.57,-625 RS1.2@2145,-625 ; RS1.2@2145,-625 2145,-620.77 RS1.2@2144.23,-620 2144.23,-620.77 2140,-625 RS1.2@2145,-625
NetRG2_2: RG2.2 RS2.1 RT2.2 | length 179.9
  Top Layer w15: RT2.2@2170,-445 2165,-450 2165,-485 2145,-505 RS2.1@2145,-535 RG2.2@2224.57,-535
NetRG3_1: RG3.1 RS3.2 RT3.2 | length 173.7
  Top Layer w15: RG3.1@2759.57,-775.77 2760,-776.2 RT3.2@2760,-863.21 2762.56,-865.77 RS3.2@2845,-865.77
NetRG4_1: RG4.1 RS4.2 RT4.2 | length 169.8
  Top Layer w15: RG4.1@3035,-775.43 RT4.2@3035,-852.44 3041.66,-859.1 RS4.2@3125,-859.1
OSC_3V3: C34.1 C35.1 C36.2 C79.1 C80.1 OSC1.4 R34.1 U6.2 U6.4 | length 1013.1
  Top Layer w25: C34.1@1567.14,1710 C34.1@1570,1707.14 ; C34.1@1580,1712.14 C34.1@1584.24,1716.38 ; C35.1@1777.84,1716.38 C35.1@1780,1718.53 1780.35,1718.18 C80.1@1780.35,1500 ; R34.1@1783.22,1410 1781.79,1411.43 1781.79,1498.57 C80.1@1780.35,1500 ; OSC1.4@1887.52,1499.53 1780.83,1499.53 C80.1@1780.35,1500
  Top Layer w30: U6.2@1177.95,1710 U6.4@1422.05,1710 C34.1@1567.14,1710 ; C34.1@1584.24,1716.38 C36.2@1675,1716.38 C35.1@1777.84,1716.38
PA_3V3: C28.1 C29.1 C30.2 C100.1 C101.2 C102.1 L12.2 U5.2 U5.4 | length 2850
  Top Layer w30: L12.2@4820,1053.54 4863.54,1053.54 v1(4880,1070) ; v1(4880,1245) 4905.96,1245 4923.53,1262.57 C100.1@4923.53,1430 ; C100.1@4922.07,1430 C102.1@4922.07,1545 ; v1(5331.47,-435) 5340,-443.53 U5.4@5340,-759.12 U5.2@5340,-1003.22
  Power w30: v1(4880,1245) v1(4880,1070) 4880,900 5345,435 5345,8.66 5331.47,-4.87 v1(5331.47,-435)
PICO2_5V: J9.20 L1.4 L2.4 L3.4 L4.4 L5.4 L6.4 L7.4 | length 14397.2
  Top Layer w30: v1(2093.82,-1208.13) 2136.66,-1250.97 L2.4@2136.66,-1341.62 ; v1(3528.82,-1198.13) 3555.69,-1225 3636.89,-1225 3656.66,-1244.77 3656.66,-1325.97 L3.4@3656.66,-1366.62
  Power w50: v1@-75.6,-1430 185,-1430 433.39,-1181.61 433.39,-1066.61 ; v1(606.51,1037.16) 606.51,1268.49 318.22,1556.78 220,1556.78 ; v1(606.51,1647.16) 587.95,1665.71 320,1665.71 320,1656.78 220,1556.78 ; J9.20@1900,0 1900,-108.93 1870.71,-138.22 300,-138.22 ; v1(3528.82,-1198.13) 3646.13,-1315.43 3646.13,-1559.04 3543.82,-1661.34 ; v1@5309.41,-1535.34 5183.41,-1661.34 3543.82,-1661.34 ; 220,1556.78 -75.71,1556.78 -105,1527.49 -105,-138.22 300,-138.22 ; 300,-138.22 300,-933.22 433.39,-1066.61 ; 433.39,-1066.61 658.82,-1292.04 v1(658.82,-1398.13) 927.04,-1666.34 1309.13,-1666.34 1633.82,-1341.65 v1(1633.82,-1213.13) 1751.13,-1330.43 1751.13,-1477.59 1914.16,-1640.63 1955.59,-1640.63 2211.13,-1385.09 2211.13,-1325.43 v1(2093.82,-1208.13) 2199.91,-1208.13 2653.13,-1661.34 3543.82,-1661.34
  other v1: 5310,-1535.93 -75.6,-1429.75
PLL_3V3: C40.1 C41.1 C42.2 L9.1 L10.1 PLL1.6 PLL1.10 PLL1.16 PLL1.17 PLL1.26 PLL1.28 PLL1.32 U7.2 U7.4 | length 3232.2
  Top Layer w15: 2749.21,1219.21 2752.5,1222.5 2782.92,1222.5 2783.95,1221.48 PLL1.26@2792.26,1221.48 ; 2750,1179.5 2752,1177.5 2782.39,1177.5 2782.47,1177.58 2797.93,1177.58 PLL1.28@2800.35,1180 ; PLL1.17@2963.9,1264.49 2963.9,1258.82 2983.82,1238.9 PLL1.16@2989.49,1238.9 2990.59,1240 v1(3040,1240) ; PLL1.10@2989.49,1120.79 2991.75,1118.52 3007.53,1118.52 3036.05,1090 v1(3065,1090) ; L10.1@3136.73,1185 3136.73,1115.3 3137.03,1115 v1(3185,1115)
  Top Layer w19: v1(2720,1090) 2720.57,1090.57 2755.22,1090.57 2765.75,1101.1 PLL1.32@2794.26,1101.1 ; 2749.21,1219.21 v1(2730,1200) 2730,1199.19 2737.05,1192.14 2737.05,1186.9 2744.45,1179.5 2750,1179.5 ; PLL1.28@2800.35,1180 PLL1.28@2800.51,1179.84 ; v1(2923.21,1025) 2923.21,1025.81 2924.34,1026.94 PLL1.6@2924.34,1069.26
  Top Layer w30: U7.2@1177.95,1105 U7.4@1422.05,1105 1423.48,1103.57 1544.37,1103.57 1544.42,1103.62 1544.42,1119.15 C40.1@1560,1103.57 1563.57,1100 C42.2@1645,1100 ; C42.2@1645,1104.02 1647.72,1106.73 1651.73,1106.73 1655,1110 1805,1110 v1(1825,1130)
  Power w30: v1(1825,1130) 1895,1200 v1(2730,1200) 2730,1175 2694.93,1139.93 2694.93,1115.07 2785,1025 3065,1025 ; v1(3040,1240) 3090,1240 3183.66,1146.34 3183.66,1116.34 v1(3185,1115) 3185,1051.24 3109.3,975.55 3084.45,975.55 3065,995 3065,1025 ; v1(3065,1090) 3065,1025
QIN_N: C47.2 J1.1 R2.2 RS2.2 U8.5 | length 1127.1
  Top Layer w15: U8.5@1124.06,-460.51 1124.06,-433.19 1135,-422.25 1135,-395 1180,-350 1335,-350 1505,-520 J1.1@1625,-520 1722.24,-520 1737.83,-535.59 C47.2@1770,-535.59 ; C47.2@1770,-535 1840,-535 RS2.2@2096.54,-535
QIN_P: C48.2 J1.2 R3.2 RS1.1 U8.1 | length 1128.6
  Top Layer w15: U8.1@1149.27,-544.78 1184.33,-544.78 1200,-560.45 1200,-670 1215,-685 1616.21,-685 1625,-676.21 J1.2@1625,-620 1770,-620 1850,-620 RS1.1@2095.77,-620
QOUT_N: J2.3 R17.1 RF4.1 U9.11 | length 3179.2
  Top Layer w15: v1(2280,-265) R17.1@2280,-190.87 ; U9.11@2955,-545.63 3033.59,-545.63 3042.38,-536.84 3042.38,-525.22 3052.6,-515 RF4.1@3054.57,-515 3054.57,-474.57 v1(3040,-460) 3075,-425 3305,-425 3332.5,-452.5 3332.5,-742.5 3350,-760 J2.3@3425,-760
  Bottom Layer w15: v1(2280,-265) 2280,-360 2280.11,-360.11 2300,-380 2317.5,-380 2317.5,-473.28 2352.5,-473.28 2352.5,-191.58 2387.5,-191.58 2387.5,-473.28 2422.5,-473.28 2422.5,-191.58 2457.5,-191.58 2457.5,-473.28 2492.5,-473.28 2492.5,-380 2500,-380 2636.77,-380 2645.27,-371.5 2664.73,-371.5 2673.23,-380 2960,-380 v1(3040,-460)
QOUT_P: J2.4 R19.1 RF2.2 U9.10 | length 2848.9
  Top Layer w15: RF2.2@2910,-785.43 2954.57,-785.43 v1(2960,-780) ; U9.10@2955,-565.32 3001.08,-565.32 3009.88,-574.12 v1(3013.67,-574.12) ; v1(4860,-245) R19.1@4860,-185.87
  Bottom Layer w15: v1(2960,-780) 3013.67,-726.33 v1(3013.67,-574.12) ; J2.4@3425,-660 3099.55,-660 v1(3013.67,-574.12) ; v1(4860,-245) 4860,-275 4790,-345 3395,-345 3165.88,-574.12 v1(3013.67,-574.12)
RFOUT1: C97.1 IQM1.16 | length 65.6
  Top Layer w15: IQM1.16@3882.56,1171.61 3883.37,1170.81 3946.64,1170.81 C97.1@3947.44,1170
RFOUT_FILT: BPF1.4 C103.1 J7.1 | length 233.3
  Top Layer w15: BPF1.4@4369.69,1181.34 4371.02,1180 C103.1@4602.44,1180
RFOUT_FILT1: C103.2 C105.2 PA1.1 | length 407
  Top Layer w15: C103.2@4657.56,1180 4705,1180 4773.19,1111.81 4965,1111.81 5033.78,1111.81 PA1.1@5035.59,1113.62
pads on no net: IQM1.1 IQM1.6 J8.1 J8.2 J8.4 J8.5 J8.6 J8.7 J8.9 J8.10 J8.11 J8.12 J8.20 J9.9 J9.10 J9.11 J9.12 J9.14 J9.15 J9.16 J9.17 J9.19 PLL1.14 PLL1.15 PLL1.33 U8.4 U8.16 U9.2 U9.4 U9.7 U9.9 U9.12 U9.14 U9.17 U9.19 U9.HTAB
copper on no net:
  other v2: 2851.69,1126.69 2895,1126.69 2938.31,1126.69 2851.69,1170 2895,1170 2938.31,1170 2851.69,1213.31 2895,1213.31 2938.31,1213.31

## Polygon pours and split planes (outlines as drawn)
GND on GND "GND" (solid, pour order 1): -320,-2435 5575,-2435 5575,3280 -320,3280
GND on Power "Power" (solid, pour order 2): -320,-2435 5575,-2435 5575,3280 -320,3280
GND on Bottom Layer "Bottom Layer" (solid, pour order 3): -320,-2435 5575,-2435 5575,3280 -320,3280
GND on Top Layer "Top layer" (solid, pour order 0): -320,-2435 5575,-2435 5575,3280 -320,3280

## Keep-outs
Keep-Out Layer:
  lines w10: -320,-1816.32 ccw(c-171.08,-1816.32) -171.08,-1965.24 5429.83,-1965 ccw(c5429.83,-1819.6) 5575.23,-1819.6 5575.03,1930 ; -320,-1815 -317.68,1944.11 cw(c-186.81,1944.11) -186.81,2074.98 5431.44,2075 cw(c5430.72,1930.72) 5575,1930

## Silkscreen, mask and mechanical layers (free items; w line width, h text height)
Top Overlay:
  text "I +" at 3765,740 h60 r90
  text "I +" at 3865,740 h60 r90
  text "Q-" at 3665.06,735 h60 r90
  text "Q+" at 3965.06,735 h60 r90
